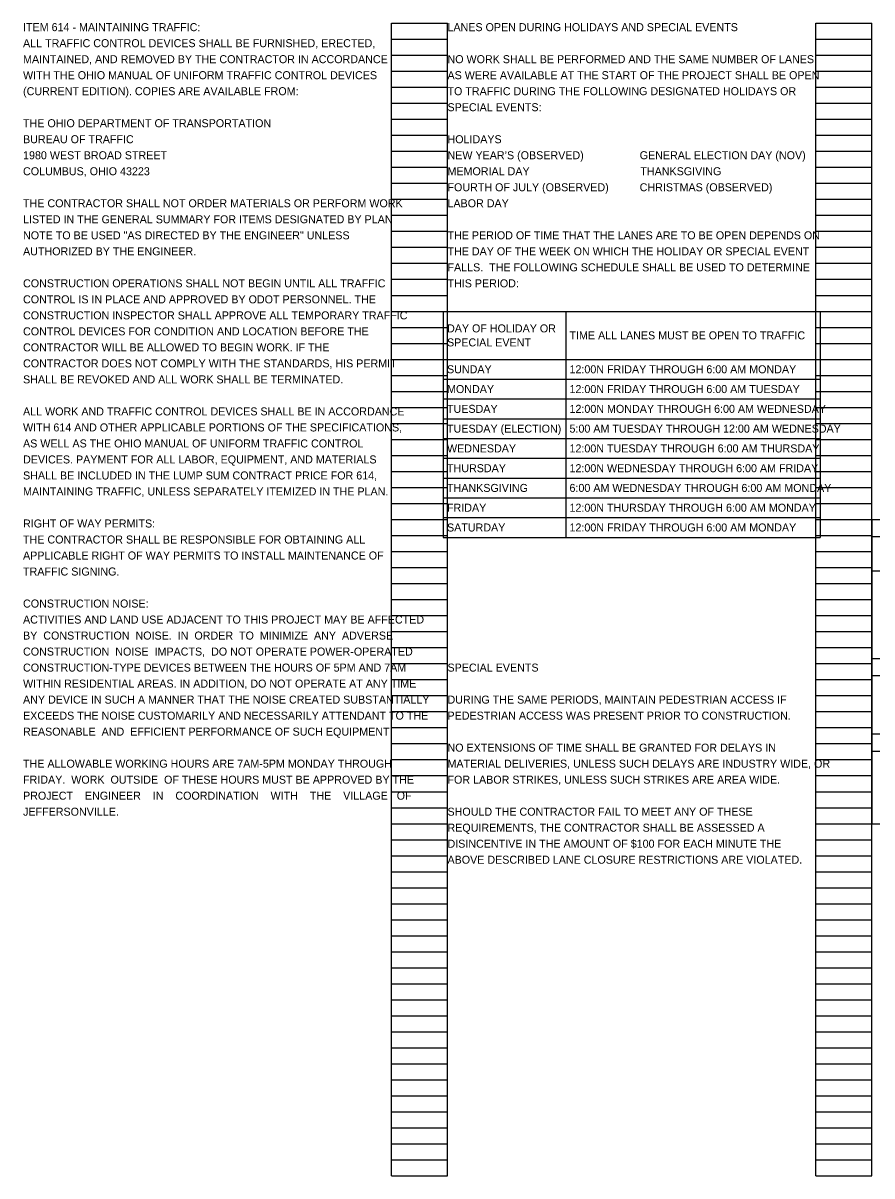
# Model space of a CAD drawing. Extents: x 37613.4 to 37668.4, y 18853.7 to 18946.8.
# Drawn here: x 37638.8 to 37653.64, y 18926.59 to 18946.76 of the extents above; entities that cross this region are included whole.
import ezdxf

# ---------------------------------------------------------------- set-up
doc = ezdxf.new("R2010")
doc.units = 0
for name, color, linetype in [('AP_P_Airside', 7, 'Continuous'), ('SH_Data', 7, 'Continuous'), ('SH_Text', 7, 'Continuous')]:
    doc.layers.add(name, color=color, linetype=linetype)

msp = doc.modelspace()

# ---------------------------------------------------------------- linework, layer by layer
at = {"layer": 'AP_P_Airside'}
for p, q in [((37653.641, 18938.075), (37660.031, 18938.075)), ((37653.641, 18938.075), (37653.641, 18932.75)), ((37653.641, 18937.775), (37660.031, 18937.775)), ((37653.641, 18937.175), (37660.031, 18937.175)), ((37653.641, 18935.645), (37660.031, 18935.645)), ((37653.641, 18935.345), (37660.031, 18935.345)), ((37653.641, 18934.325), (37660.031, 18934.325)), ((37653.641, 18934.025), (37660.031, 18934.025)), ((37653.641, 18932.75), (37660.031, 18932.75))]:
    msp.add_line(p, q, dxfattribs=at)
at = {"layer": 'SH_Data'}
for p, q in [((37645.241, 18926.595), (37645.241, 18946.755)), ((37645.241, 18946.755), (37646.221, 18946.755)), ((37646.221, 18926.595), (37646.221, 18946.755)), ((37652.661, 18926.595), (37652.661, 18946.755)), ((37652.661, 18946.755), (37653.641, 18946.755)), ((37653.641, 18926.595), (37653.641, 18946.755)), ((37645.241, 18946.475), (37646.221, 18946.475)), ((37652.661, 18946.475), (37653.641, 18946.475)), ((37645.241, 18946.195), (37646.221, 18946.195)), ((37652.661, 18946.195), (37653.641, 18946.195)), ((37645.241, 18945.915), (37646.221, 18945.915)), ((37652.661, 18945.915), (37653.641, 18945.915)), ((37645.241, 18945.635), (37646.221, 18945.635)), ((37652.661, 18945.635), (37653.641, 18945.635)), ((37645.241, 18945.355), (37646.221, 18945.355)), ((37652.661, 18945.355), (37653.641, 18945.355)), ((37645.241, 18945.075), (37646.221, 18945.075)), ((37652.661, 18945.075), (37653.641, 18945.075)), ((37645.241, 18944.795), (37646.221, 18944.795)), ((37652.661, 18944.795), (37653.641, 18944.795)), ((37645.241, 18944.515), (37646.221, 18944.515)), ((37652.661, 18944.515), (37653.641, 18944.515)), ((37645.241, 18944.235), (37646.221, 18944.235)), ((37652.661, 18944.235), (37653.641, 18944.235)), ((37645.241, 18943.955), (37646.221, 18943.955)), ((37652.661, 18943.955), (37653.641, 18943.955)), ((37645.241, 18943.675), (37646.221, 18943.675)), ((37652.661, 18943.675), (37653.641, 18943.675)), ((37645.241, 18943.395), (37646.221, 18943.395)), ((37652.661, 18943.395), (37653.641, 18943.395)), ((37645.241, 18943.115), (37646.221, 18943.115)), ((37652.661, 18943.115), (37653.641, 18943.115)), ((37645.241, 18942.835), (37646.221, 18942.835)), ((37652.661, 18942.835), (37653.641, 18942.835)), ((37645.241, 18942.555), (37646.221, 18942.555)), ((37652.661, 18942.555), (37653.641, 18942.555)), ((37645.241, 18942.275), (37646.221, 18942.275)), ((37652.661, 18942.275), (37653.641, 18942.275)), ((37645.241, 18941.995), (37646.221, 18941.995)), ((37652.661, 18941.995), (37653.641, 18941.995)), ((37645.241, 18941.715), (37646.221, 18941.715)), ((37652.661, 18941.715), (37653.641, 18941.715)), ((37645.241, 18941.435), (37646.221, 18941.435)), ((37652.661, 18941.435), (37653.641, 18941.435)), ((37645.241, 18941.155), (37646.221, 18941.155)), ((37652.661, 18941.155), (37653.641, 18941.155)), ((37645.241, 18940.875), (37646.221, 18940.875)), ((37652.661, 18940.875), (37653.641, 18940.875)), ((37645.241, 18940.595), (37646.221, 18940.595)), ((37652.661, 18940.595), (37653.641, 18940.595)), ((37645.241, 18940.315), (37646.221, 18940.315)), ((37652.661, 18940.315), (37653.641, 18940.315)), ((37645.241, 18940.035), (37646.221, 18940.035)), ((37652.661, 18940.035), (37653.641, 18940.035)), ((37645.241, 18939.755), (37646.221, 18939.755)), ((37652.661, 18939.755), (37653.641, 18939.755)), ((37645.241, 18939.475), (37646.221, 18939.475)), ((37652.661, 18939.475), (37653.641, 18939.475)), ((37645.241, 18939.195), (37646.221, 18939.195)), ((37652.661, 18939.195), (37653.641, 18939.195)), ((37645.241, 18938.915), (37646.221, 18938.915)), ((37652.661, 18938.915), (37653.641, 18938.915)), ((37645.241, 18938.635), (37646.221, 18938.635)), ((37652.661, 18938.635), (37653.641, 18938.635)), ((37645.241, 18938.355), (37646.221, 18938.355)), ((37652.661, 18938.355), (37653.641, 18938.355)), ((37645.241, 18938.075), (37646.221, 18938.075)), ((37652.661, 18938.075), (37653.641, 18938.075)), ((37645.241, 18937.795), (37646.221, 18937.795)), ((37652.661, 18937.795), (37653.641, 18937.795)), ((37645.241, 18937.515), (37646.221, 18937.515)), ((37652.661, 18937.515), (37653.641, 18937.515)), ((37645.241, 18937.235), (37646.221, 18937.235)), ((37652.661, 18937.235), (37653.641, 18937.235)), ((37645.241, 18936.955), (37646.221, 18936.955)), ((37652.661, 18936.955), (37653.641, 18936.955)), ((37645.241, 18936.675), (37646.221, 18936.675)), ((37652.661, 18936.675), (37653.641, 18936.675)), ((37645.241, 18936.395), (37646.221, 18936.395)), ((37652.661, 18936.395), (37653.641, 18936.395)), ((37645.241, 18936.115), (37646.221, 18936.115)), ((37652.661, 18936.115), (37653.641, 18936.115)), ((37645.241, 18935.835), (37646.221, 18935.835)), ((37652.661, 18935.835), (37653.641, 18935.835)), ((37645.241, 18935.555), (37646.221, 18935.555)), ((37652.661, 18935.555), (37653.641, 18935.555)), ((37645.241, 18935.275), (37646.221, 18935.275)), ((37652.661, 18935.275), (37653.641, 18935.275)), ((37645.241, 18934.995), (37646.221, 18934.995)), ((37652.661, 18934.995), (37653.641, 18934.995)), ((37645.241, 18934.715), (37646.221, 18934.715)), ((37652.661, 18934.715), (37653.641, 18934.715)), ((37645.241, 18934.435), (37646.221, 18934.435)), ((37652.661, 18934.435), (37653.641, 18934.435)), ((37645.241, 18934.155), (37646.221, 18934.155)), ((37652.661, 18934.155), (37653.641, 18934.155)), ((37645.241, 18933.875), (37646.221, 18933.875)), ((37652.661, 18933.875), (37653.641, 18933.875)), ((37645.241, 18933.595), (37646.221, 18933.595)), ((37652.661, 18933.595), (37653.641, 18933.595)), ((37645.241, 18933.315), (37646.221, 18933.315)), ((37652.661, 18933.315), (37653.641, 18933.315)), ((37645.241, 18933.035), (37646.221, 18933.035)), ((37652.661, 18933.035), (37653.641, 18933.035)), ((37645.241, 18932.755), (37646.221, 18932.755)), ((37652.661, 18932.755), (37653.641, 18932.755)), ((37645.241, 18932.475), (37646.221, 18932.475)), ((37652.661, 18932.475), (37653.641, 18932.475)), ((37645.241, 18932.195), (37646.221, 18932.195)), ((37652.661, 18932.195), (37653.641, 18932.195)), ((37645.241, 18931.915), (37646.221, 18931.915)), ((37652.661, 18931.915), (37653.641, 18931.915)), ((37645.241, 18931.635), (37646.221, 18931.635)), ((37652.661, 18931.635), (37653.641, 18931.635)), ((37645.241, 18931.355), (37646.221, 18931.355)), ((37652.661, 18931.355), (37653.641, 18931.355)), ((37645.241, 18931.075), (37646.221, 18931.075)), ((37652.661, 18931.075), (37653.641, 18931.075)), ((37645.241, 18930.795), (37646.221, 18930.795)), ((37652.661, 18930.795), (37653.641, 18930.795)), ((37645.241, 18930.515), (37646.221, 18930.515)), ((37652.661, 18930.515), (37653.641, 18930.515)), ((37645.241, 18930.235), (37646.221, 18930.235)), ((37652.661, 18930.235), (37653.641, 18930.235)), ((37645.241, 18929.955), (37646.221, 18929.955)), ((37652.661, 18929.955), (37653.641, 18929.955)), ((37645.241, 18929.675), (37646.221, 18929.675)), ((37652.661, 18929.675), (37653.641, 18929.675)), ((37645.241, 18929.395), (37646.221, 18929.395)), ((37652.661, 18929.395), (37653.641, 18929.395)), ((37645.241, 18929.115), (37646.221, 18929.115)), ((37652.661, 18929.115), (37653.641, 18929.115)), ((37645.241, 18928.835), (37646.221, 18928.835)), ((37652.661, 18928.835), (37653.641, 18928.835)), ((37645.241, 18928.555), (37646.221, 18928.555)), ((37652.661, 18928.555), (37653.641, 18928.555)), ((37645.241, 18928.275), (37646.221, 18928.275)), ((37652.661, 18928.275), (37653.641, 18928.275)), ((37645.241, 18927.995), (37646.221, 18927.995)), ((37652.661, 18927.995), (37653.641, 18927.995)), ((37645.241, 18927.715), (37646.221, 18927.715)), ((37652.661, 18927.715), (37653.641, 18927.715)), ((37645.241, 18927.435), (37646.221, 18927.435)), ((37652.661, 18927.435), (37653.641, 18927.435)), ((37645.241, 18927.155), (37646.221, 18927.155)), ((37652.661, 18927.155), (37653.641, 18927.155)), ((37645.241, 18926.875), (37646.221, 18926.875)), ((37652.661, 18926.875), (37653.641, 18926.875)), ((37645.241, 18926.595), (37646.221, 18926.595)), ((37652.661, 18926.595), (37653.641, 18926.595))]:
    msp.add_line(p, q, dxfattribs=at)
at = {"layer": 'SH_Text'}
for p, q in [((37646.147, 18941.715), (37652.735, 18941.715)), ((37646.147, 18941.715), (37646.147, 18937.762)), ((37648.288, 18941.715), (37648.288, 18937.762)), ((37652.735, 18941.715), (37652.735, 18937.762)), ((37646.147, 18940.875), (37652.735, 18940.875)), ((37646.147, 18940.529), (37652.735, 18940.529)), ((37646.147, 18940.183), (37652.735, 18940.183)), ((37646.147, 18939.837), (37652.735, 18939.837)), ((37646.147, 18939.491), (37652.735, 18939.491)), ((37646.147, 18939.145), (37652.735, 18939.145)), ((37646.147, 18938.799), (37652.735, 18938.799)), ((37646.147, 18938.454), (37652.735, 18938.454)), ((37646.147, 18938.108), (37652.735, 18938.108)), ((37646.147, 18937.762), (37652.735, 18937.762))]:
    msp.add_line(p, q, dxfattribs=at)

# ---------------------------------------------------------------- texts
at = {"layer": 'SH_Data'}
for s, p in [('LANES OPEN DURING HOLIDAYS AND SPECIAL EVENTS', (37646.221, 18946.615)), ('NO WORK SHALL BE PERFORMED AND THE SAME NUMBER OF LANES ', (37646.221, 18946.055)), ('AS WERE AVAILABLE AT THE START OF THE PROJECT SHALL BE OPEN ', (37646.221, 18945.775)), ('TO TRAFFIC DURING THE FOLLOWING DESIGNATED HOLIDAYS OR ', (37646.221, 18945.495)), ('SPECIAL EVENTS:', (37646.221, 18945.215)), ('HOLIDAYS', (37646.221, 18944.655)), ('NEW YEAR’S (OBSERVED)', (37646.221, 18944.375)), ('GENERAL ELECTION DAY (NOV)', (37649.581, 18944.375)), ('MEMORIAL DAY', (37646.221, 18944.095)), ('           THANKSGIVING', (37649.021, 18944.095)), ('FOURTH OF JULY (OBSERVED)', (37646.221, 18943.815)), ('CHRISTMAS (OBSERVED)', (37649.581, 18943.815)), ('LABOR DAY', (37646.221, 18943.535)), ('THE PERIOD OF TIME THAT THE LANES ARE TO BE OPEN DEPENDS ON ', (37646.221, 18942.975)), ('THE DAY OF THE WEEK ON WHICH THE HOLIDAY OR SPECIAL EVENT ', (37646.221, 18942.695)), ('FALLS.  THE FOLLOWING SCHEDULE SHALL BE USED TO DETERMINE ', (37646.221, 18942.415)), ('THIS PERIOD:', (37646.221, 18942.135)), ('SPECIAL EVENTS', (37646.221, 18935.415)), ('DURING THE SAME PERIODS, MAINTAIN PEDESTRIAN ACCESS IF ', (37646.221, 18934.855)), ('PEDESTRIAN ACCESS WAS PRESENT PRIOR TO CONSTRUCTION. ', (37646.221, 18934.575)), ('NO EXTENSIONS OF TIME SHALL BE GRANTED FOR DELAYS IN ', (37646.221, 18934.015)), ('MATERIAL DELIVERIES, UNLESS SUCH DELAYS ARE INDUSTRY WIDE, OR ', (37646.221, 18933.735)), ('FOR LABOR STRIKES, UNLESS SUCH STRIKES ARE AREA WIDE.', (37646.221, 18933.455)), ('SHOULD THE CONTRACTOR FAIL TO MEET ANY OF THESE ', (37646.221, 18932.895)), ('REQUIREMENTS, THE CONTRACTOR SHALL BE ASSESSED A ', (37646.221, 18932.615)), ('DISINCENTIVE IN THE AMOUNT OF $100 FOR EACH MINUTE THE ', (37646.221, 18932.335)), ('ABOVE DESCRIBED LANE CLOSURE RESTRICTIONS ARE VIOLATED.', (37646.221, 18932.055))]:
    msp.add_text(s, height=0.14, dxfattribs=at).set_placement(p)
at = {"layer": 'SH_Text'}
for s, p in [('ITEM 614 - MAINTAINING TRAFFIC:', (37638.801, 18946.615)), ('ALL TRAFFIC CONTROL DEVICES SHALL BE FURNISHED, ERECTED, ', (37638.801, 18946.335)), ('MAINTAINED, AND REMOVED BY THE CONTRACTOR IN ACCORDANCE ', (37638.801, 18946.055)), ('WITH THE OHIO MANUAL OF UNIFORM TRAFFIC CONTROL DEVICES ', (37638.801, 18945.775)), ('(CURRENT EDITION). COPIES ARE AVAILABLE FROM:', (37638.801, 18945.495)), ('THE OHIO DEPARTMENT OF TRANSPORTATION', (37638.801, 18944.935)), ('BUREAU OF TRAFFIC', (37638.801, 18944.655)), ('1980 WEST BROAD STREET', (37638.801, 18944.375)), ('COLUMBUS, OHIO 43223', (37638.801, 18944.095)), ('THE CONTRACTOR SHALL NOT ORDER MATERIALS OR PERFORM WORK ', (37638.801, 18943.535)), ('LISTED IN THE GENERAL SUMMARY FOR ITEMS DESIGNATED BY PLAN ', (37638.801, 18943.255)), ('NOTE TO BE USED "AS DIRECTED BY THE ENGINEER" UNLESS ', (37638.801, 18942.975)), ('AUTHORIZED BY THE ENGINEER.', (37638.801, 18942.695)), ('CONSTRUCTION OPERATIONS SHALL NOT BEGIN UNTIL ALL TRAFFIC ', (37638.801, 18942.135)), ('CONTROL IS IN PLACE AND APPROVED BY ODOT PERSONNEL. THE ', (37638.801, 18941.855)), ('CONSTRUCTION INSPECTOR SHALL APPROVE ALL TEMPORARY TRAFFIC ', (37638.801, 18941.575)), ('DAY OF HOLIDAY OR ', (37646.213, 18941.347)), ('CONTROL DEVICES FOR CONDITION AND LOCATION BEFORE THE ', (37638.801, 18941.295)), ('TIME ALL LANES MUST BE OPEN TO TRAFFIC', (37648.354, 18941.225)), ('CONTRACTOR WILL BE ALLOWED TO BEGIN WORK. IF THE ', (37638.801, 18941.015)), ('SPECIAL EVENT', (37646.213, 18941.102)), ('CONTRACTOR DOES NOT COMPLY WITH THE STANDARDS, HIS PERMIT ', (37638.801, 18940.735)), ('SUNDAY', (37646.213, 18940.632)), ('12:00N FRIDAY THROUGH 6:00 AM MONDAY', (37648.354, 18940.632)), ('SHALL BE REVOKED AND ALL WORK SHALL BE TERMINATED.', (37638.801, 18940.455)), ('MONDAY', (37646.213, 18940.286)), ('12:00N FRIDAY THROUGH 6:00 AM TUESDAY', (37648.354, 18940.286)), ('TUESDAY', (37646.213, 18939.94)), ('12:00N MONDAY THROUGH 6:00 AM WEDNESDAY', (37648.354, 18939.94)), ('ALL WORK AND TRAFFIC CONTROL DEVICES SHALL BE IN ACCORDANCE ', (37638.801, 18939.895)), ('WITH 614 AND OTHER APPLICABLE PORTIONS OF THE SPECIFICATIONS, ', (37638.801, 18939.615)), ('TUESDAY (ELECTION)', (37646.213, 18939.594)), ('5:00 AM TUESDAY THROUGH 12:00 AM WEDNESDAY', (37648.354, 18939.594)), ('AS WELL AS THE OHIO MANUAL OF UNIFORM TRAFFIC CONTROL ', (37638.801, 18939.335)), ('WEDNESDAY', (37646.213, 18939.248)), ('12:00N TUESDAY THROUGH 6:00 AM THURSDAY', (37648.354, 18939.248)), ('DEVICES. PAYMENT FOR ALL LABOR, EQUIPMENT, AND MATERIALS ', (37638.801, 18939.055)), ('SHALL BE INCLUDED IN THE LUMP SUM CONTRACT PRICE FOR 614, ', (37638.801, 18938.775)), ('THURSDAY', (37646.213, 18938.902)), ('12:00N WEDNESDAY THROUGH 6:00 AM FRIDAY', (37648.354, 18938.902)), ('THANKSGIVING', (37646.213, 18938.557)), ('6:00 AM WEDNESDAY THROUGH 6:00 AM MONDAY', (37648.354, 18938.557)), ('MAINTAINING TRAFFIC, UNLESS SEPARATELY ITEMIZED IN THE PLAN.', (37638.801, 18938.495)), ('FRIDAY', (37646.213, 18938.211)), ('12:00N THURSDAY THROUGH 6:00 AM MONDAY', (37648.354, 18938.211)), ('RIGHT OF WAY PERMITS:', (37638.801, 18937.935)), ('SATURDAY', (37646.213, 18937.865)), ('12:00N FRIDAY THROUGH 6:00 AM MONDAY', (37648.354, 18937.865)), ('THE CONTRACTOR SHALL BE RESPONSIBLE FOR OBTAINING ALL ', (37638.801, 18937.655)), ('APPLICABLE RIGHT OF WAY PERMITS TO INSTALL MAINTENANCE OF ', (37638.801, 18937.375)), ('TRAFFIC SIGNING.', (37638.801, 18937.095)), ('CONSTRUCTION NOISE:', (37638.801, 18936.535)), ('ACTIVITIES AND LAND USE ADJACENT TO THIS PROJECT MAY BE AFFECTED', (37638.801, 18936.255)), ('BY  CONSTRUCTION  NOISE.  IN  ORDER  TO  MINIMIZE  ANY  ADVERSE', (37638.801, 18935.975)), ('CONSTRUCTION  NOISE  IMPACTS,  DO NOT OPERATE POWER-OPERATED', (37638.801, 18935.695)), ('CONSTRUCTION-TYPE DEVICES BETWEEN THE HOURS OF 5PM AND 7AM', (37638.801, 18935.415)), ('WITHIN RESIDENTIAL AREAS. IN ADDITION, DO NOT OPERATE AT ANY TIME', (37638.801, 18935.135)), ('ANY DEVICE IN SUCH A MANNER THAT THE NOISE CREATED SUBSTANTIALLY', (37638.801, 18934.855)), ('EXCEEDS THE NOISE CUSTOMARILY AND NECESSARILY ATTENDANT TO THE', (37638.801, 18934.575)), ('REASONABLE  AND  EFFICIENT PERFORMANCE OF SUCH EQUIPMENT.', (37638.801, 18934.295)), ('THE ALLOWABLE WORKING HOURS ARE 7AM-5PM MONDAY THROUGH', (37638.801, 18933.735)), ('FRIDAY.  WORK  OUTSIDE  OF THESE HOURS MUST BE APPROVED BY THE', (37638.801, 18933.455)), ('PROJECT    ENGINEER    IN    COORDINATION    WITH    THE    VILLAGE   OF', (37638.801, 18933.175)), ('JEFFERSONVILLE.', (37638.801, 18932.895))]:
    msp.add_text(s, height=0.14, dxfattribs=at).set_placement(p)

doc.saveas('drawing.dxf')
